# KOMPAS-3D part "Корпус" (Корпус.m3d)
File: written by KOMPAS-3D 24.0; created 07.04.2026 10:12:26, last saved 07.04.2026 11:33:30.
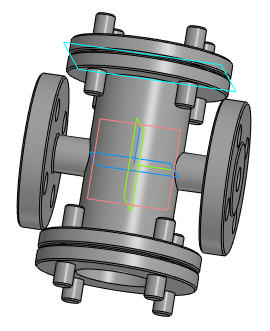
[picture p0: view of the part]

Document properties: Автор: Main; Полное имя файла: D:\DN.ru Аутсерс\Стекло смотровое DN.ru\Исходники\Стекло смотровое DN.ru SG2-34G-F тип В ГОСТ 21836-2021 Ду15 Ру40, углеродистая сталь, фланцевое\Корпус.m3d

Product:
- Part/product: Корпус
    Масса: 2.761283

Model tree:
1. Эскиз:1
2. Элемент выдавливания:1
     Толщина стенки 1 = 4
3. Эскиз:2  (with: Грань.Элемент выдавливания:1, Ребро.Элемент выдавливания:1)
4. Элемент выдавливания:2
5. Эскиз:3  (with: Грань.Элемент выдавливания:1, Ребро.Элемент выдавливания:2)
6. Элемент выдавливания:3
     Расстояние 2 = -2.15622
7. Фаска:2  (with: Ребро.Элемент выдавливания:3)
     Угол = 45; Длина 1 = 1; Длина 2 = 1
8. Фаска:3  (with: Ребро.Элемент выдавливания:2, Ребро.Элемент выдавливания:3)
     Угол = 45; Длина 1 = 1; Длина 2 = 1
9. Зеркальный массив:2
10. Экземпляр ( 1 )
11. Экземпляр ( 2 )  (with: Элемент выдавливания:2, Элемент выдавливания:3, Фаска:3, Фаска:2)
12. Эскиз:4
13. Элемент выдавливания:4
     Толщина стенки 1 = 4
14. Эскиз:5  (with: Грань.Элемент выдавливания:4, Ребро.Элемент выдавливания:4)
15. Элемент выдавливания:5
16. Эскиз:6  (with: Грань.Элемент выдавливания:4, Ребро.Элемент выдавливания:4)
17. Элемент выдавливания:6
     Расстояние 2 = 120
18. Эскиз:7  (with: Грань.Элемент выдавливания:1, Ребро.Элемент выдавливания:1)
19. Элемент выдавливания:7
     Расстояние 2 = 130
20. Эскиз:8  (with: Грань.Элемент выдавливания:4)
21. Элемент выдавливания:8
     Расстояние 1 = 50
22. Смещенная плоскость:1  (with: Грань.Элемент выдавливания:4)
     Расстояние = 1
23. Эскиз:9  (with: Ребро.Элемент выдавливания:4, Ребро.Элемент выдавливания:5)
24. Элемент выдавливания:9
     Расстояние 1 = 10
25. Фаска:5  (with: Ребро.Элемент выдавливания:9)
     Угол = 45; Длина 1 = 5; Длина 2 = 5
26. Фаска:6  (with: Ребро.Элемент выдавливания:8, Ребро.Элемент выдавливания:5, Ребро.Элемент выдавливания:9)
     Угол = 45; Длина 1 = 1; Длина 2 = 1
27. Зеркальный массив:5  (with: Экземпляр ( 1 ), Экземпляр ( 2 ), Элемент выдавливания:9, Элемент выдавливания:5, Элемент выдавливания:8, Фаска:6)

Expressions: 45+1
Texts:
  Шаг 2
  Шаг 1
